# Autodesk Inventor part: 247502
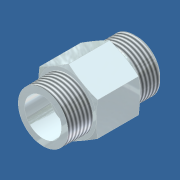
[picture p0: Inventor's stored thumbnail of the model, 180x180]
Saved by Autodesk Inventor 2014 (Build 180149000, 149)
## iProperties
Shininess: 20.0
Length Units: 11272
Angle Units: 11279
Time Units: 11290
Mass Units: 11286
Length Display Precision: 3
Angle Display Precision: 2
Company: Autodesk, Inc.
Created: 2001-12
Part Number: 247502
Material: Stainless Steel 316
Description: FITTING; ST-BC912-(SS)
Document SubType Name: Modeling
Designer: Autodesk, Inc.
Density: 8.182 g/cm^3
Mass: 209.688 g
Surface Area: 91.851 cm^2
Volume: 25.6279 cm^3
Appearance: Stainless Steel
Density: 7.86
Volumn: 5.818506058552819
Area: 35.84085697721723
PropertySet Name: Model Information
Control State: 0
Master: False
Checked Out: False
Last Check In By: JT
Last Check In Date: 2003-06-20
MODEL - 1: ---
MODEL - 2: ---
RAW MATERIAL: --------
SCALE:: 1=??
SIZE: 00 x 00 x 00
SUB-ASSY - 1: ------
SUB-ASSY - 1 - QUA: 1
SUB-ASSY - 2: ------
SUB-ASSY - 2 - QUA: 1
SYM. TO:: N/A
TEMPLATE CREATION: -- / __-__-__
Title: FITTING; ST-BC912-(SS)
Author: Autodesk, Inc.
Comments: ORING = -018
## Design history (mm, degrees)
derived "ST-BC9.ipt"
body "Solid1"
tag "TaggingFeature2"
feature "Solid1::ST-BC9.ipt" dims "ScaleForDerivedMember" = 10
